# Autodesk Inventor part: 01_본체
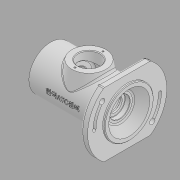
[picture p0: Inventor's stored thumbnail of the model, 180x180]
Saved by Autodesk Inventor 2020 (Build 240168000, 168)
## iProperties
Created: 2022-05
Part Number: 01_본체
Material: 일반
Document SubType Name: Modeling
Designer: User
Density: 1 g/cm^3
Appearance: 기본값
Author: User
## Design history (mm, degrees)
sketch "스케치1"
  geometry: L1 (0, 0)-(115, 0); L2 (0, 0)-(0, 32); L3 (0, 32)-(102, 32); L4 (102, 32)-(102, 58); L5 (102, 58)-(112, 58); L6 (112, 58)-(112, 36); L7 (112, 36)-(115, 36); L8 (115, 36)-(115, 0); L9 (0, 22.5)-(8, 22.5); L10 (8, 22.5)-(8, 24); L11 (8, 24)-(11, 24); L12 (11, 24)-(11, 22.5); L13 (11, 22.5)-(22, 22.5); L14 (22, 22.5)-(22, 17.5); L15 (22, 17.5)-(24.25, 17.5); L16 (24.25, 17.5)-(24.25, 18.5); L17 (24.25, 18.5)-(26, 18.5); L18 (26, 18.5)-(26, 17.5); L19 (26, 17.5)-(37, 17.5); L20 (37, 17.5)-(37, 27); L21 (37, 27)-(75, 27); L22 (75, 27)-(75, 17.5); L23 (75, 17.5)-(86, 17.5); L24 (86, 17.5)-(86, 15); L25 (86, 15)-(91, 15); L26 (91, 15)-(91, 11); L27 (91, 11)-(93.7, 11); L28 (93.7, 11)-(93.7, 15); L29 (101, 20)-(115, 30); L30 (100.3, 15)-(93.7, 15); L31 (101, 20)-(101, 15.404); L32 (101, 15.404)-(100.3, 15)
  constraints: 65 end point, 23 perpendicular, 8 point on line, 2 vertical, 1 horizontal, 1 parallel
  dimensions: "d0" = 115 distance of L1.start L1.end; "d1" = 102 distance of L2.end L3.end; "d2" = 3 distance of L6.end L7.end; "d3" = 72 diameter of L7 L1; "d4" = 64 diameter of L3 L1; "d5" = 116 diameter of L5 L1; "d6" = 14 distance from line of L8 L29.start; "d7" = 60 diameter of L29.end L1; "d8" = 40 diameter of L29.start L1; "d9" = 30 diameter of L30 L1; "d10" = 30 deg angle of L30 L32; "d11" = 0.7 horizontal distance of L30.start L31.end; "d12" = 7.3 distance between parallel lines of L28 L31; "d13" = 22 diameter of L27 L1; "d14" = 5 distance of L24.end L25.end; "d15" = 11 distance of L22.end L23.end; "d16" = 38 distance of L20.end L21.end; "d17" = 11 distance of L18.end L19.end; "d18" = 30 diameter of L25 L1; "d19" = 35 diameter of L23 L1; "d20" = 54 diameter of L21 L1; "d21" = 37 diameter of L17 L1; "d22" = 4 distance from line of L14.end L18; "d23" = 1.75 distance of L16.end L17.end; "d24" = 8 distance of L9.start L9.end; "d25" = 3 distance of L10.end L11.end; "d26" = 22 distance between parallel lines of L14 L2; "d27" = 45 diameter of L9 L1; "d28" = 48 diameter of L11 L1
revolve "회전1" sketch "스케치1" stored, may be unused: angle "d29" = 90 deg
sketch "스케치2"
  geometry: L1 (-33.985, 47)-(33.985, 47); L2 (-58, 0)-(58, 0); L3 (-33.985, -47)-(33.985, -47); A1 r 58 centre (0, 0) between (-33.985, 47) and (33.985, 47) reference; 2 further points
  constraints: 6 end point, 6 point on circle, 2 horizontal, 1 coincident, 1 midpoint, 1 parallel, 1 other
  dimensions: "d30" = 94 distance between parallel lines of L3 L1
extrude "돌출1" cut sketch "스케치2" extent not by distance; stored distance "d31" = 0; taper "d32" = 0 deg
sketch "스케치3"
  geometry: L1 (33.985, -47)-(-33.985, -47) reference; L2 (-33.985, 47)-(33.985, 47) reference; L3 (0, 0)-(48, 0); L4 (0, 0)-(36.77, 30.854); L5 (0, 0)-(-48, 0); L6 (0, 0)-(-36.77, -30.854); C1 r 36 at (0, 0) reference; A1 r 58 centre (0, 0) between (-33.985, 47) and (-33.985, -47) reference; A2 r 58 centre (0, 0) between (33.985, -47) and (33.985, 47) reference; A3 r 48 centre (0, 0) between (48, 0) and (36.77, 30.854); 2 further points
  constraints: 8 end point, 4 point on circle, 3 coincident, 2 horizontal, 1 centre point
  dimensions: "d33" = 48 radius of A3; "d34" = 40 deg angle of L3 L4; "d35" = 40 deg angle of L6 L5
hole "구멍1" sketch "스케치3" at (36.77, 30.854), (-36.77, -30.854) diameter "d36" = 8; stored, may be unused: countersink angle "d40" = 90 deg, drill point angle "d42" = 118 deg; dims "d37" = 12, "d38" = 4, "d39" = 2, "d41" = 8
sketch "스케치4"
  geometry: L1 (33.985, -47)-(-33.985, -47) reference; L2 (-33.985, 47)-(33.985, 47) reference; L3 (-48, 0)-(48, 0); C1 r 4 at (36.77, 30.854) reference; C2 r 4 at (-36.77, -30.854) reference; C3 r 36 at (0, 0) reference; A1 r 58 centre (0, 0) between (-33.985, 47) and (-33.985, -47) reference; A2 r 58 centre (0, 0) between (33.985, -47) and (33.985, 47) reference; A3 r 48 centre (0, 0) between (36.77, 30.854) and (-48, 0); A4 r 48 centre (0, 0) between (48, 0) and (36.77, 30.854); A5 r 52 centre (0, 0) between (52, 0) and (39.834, 33.425); A6 r 44 centre (0, 0) between (44, 0) and (33.706, 28.283); A7 r 4 centre (48, 0) between (44, 0) and (52, 0); A8 r 4 centre (36.77, 30.854) between (39.834, 33.425) and (33.706, 28.283); A9 r 48 centre (0, 0) between (-48, 0) and (-36.77, -30.854); A10 r 52 centre (0, 0) between (-52, 0) and (-39.834, -33.425); A11 r 44 centre (0, 0) between (-44, 0) and (-33.706, -28.283); A12 r 4 centre (-48, 0) between (-44, 0) and (-52, 0); A13 r 4 centre (-36.77, -30.854) between (-39.834, -33.425) and (-33.706, -28.283); 6 further points
  constraints: 23 point on circle, 11 centre point, 8 tangent, 4 coincident, 2 concentric, 2 end point, 1 horizontal, 1 midpoint
extrude "돌출2" cut sketch "스케치4" distance "d43" = 4.4; taper "d44" = 0 deg
sketch "스케치5"
  geometry: A1 r 4 centre (48, 0) between (44, 0) and (52, 0) reference; A2 r 52 centre (0, 0) between (52, 0) and (39.834, 33.425) reference; A3 r 4 centre (36.77, 30.854) between (33.706, 28.283) and (39.834, 33.425) reference; A4 r 44 centre (0, 0) between (44, 0) and (33.706, 28.283) reference; A5 r 4 centre (-48, 0) between (-44, 0) and (-52, 0) reference; A6 r 52 centre (0, 0) between (-52, 0) and (-39.834, -33.425) reference; A7 r 4 centre (-36.77, -30.854) between (-33.706, -28.283) and (-39.834, -33.425) reference; A8 r 44 centre (0, 0) between (-44, 0) and (-33.706, -28.283) reference; A9 r 50.25 centre (0, 0) between (50.25, 0) and (36.233, 34.818); A10 r 2.25 centre (48, 0) between (45.75, 0) and (50.25, 0); A11 r 45.75 centre (0, 0) between (45.75, 0) and (32.885, 31.806); A12 r 50.25 centre (0, 0) between (-50.25, 0) and (-40.58, -29.636); A13 r 2.25 centre (-48, 0) between (-45.75, 0) and (-50.25, 0); A14 r 45.75 centre (0, 0) between (-45.75, 0) and (-37.033, -26.862); 3 further points
  constraints: 16 point on circle, 6 centre point, 4 other
  dimensions: "d45" = 2.25 radius of A10; "d46" = 2.25 radius of A13
extrude "돌출3" cut sketch "스케치5" extent not by distance; stored distance "d47" = 0; taper "d48" = 0 deg
node "작업 평면1"
sketch "스케치6"
  geometry: C1 r 25 at (-56, 0); 1 further point
  constraints: 1 centre point, 1 horizontal alignment
  dimensions: "d50" = 25 radius of C1; "d51" = 56 distance of C1.centre point (0, 0)
extrude "돌출4" join sketch "스케치6" stored distance "d52" = 4.4; taper "d53" = 10 deg
sketch "스케치7"
  geometry: L1 (0, 0)-(0, 20.5); C1 r 25 at (0, 0) reference; 2 further points
  constraints: 2 end point, 1 coincident, 1 vertical
  dimensions: "d54" = 20.5 distance of L1.start L1.end
hole "구멍2" sketch "스케치7" at (0, 20.5) diameter "d55" = 2.62111; stored, may be unused: countersink angle "d59" = 90 deg, drill point angle "d61" = 118 deg; dims "d56" = 6, "d57" = 4, "d58" = 2, "d60" = 8
sketch "스케치8"
  geometry: C1 r 25 at (0, 0) reference; 2 further points
  constraints: 1 coincident
hole "구멍3" sketch "스케치8" at (0, 0) diameter "d65" = 32; stored, may be unused: countersink angle "d69" = 90 deg, drill point angle "d71" = 118 deg; dims "d66" = 6, "d67" = 4, "d68" = 2, "d70" = 8
fillet "모깎기1" dims "d72" = 0.5, "d73" = 0.6
fillet "모깎기2" dims "d74" = 3
chamfer "모따기1" distance "d75" = 1; stored, may be unused: second distance "d76" = 2, angle "d77" = 45 deg
fillet "모깎기3" dims "d78" = 3
node "작업 평면2"
sketch "스케치9"
  geometry: L1 (61, -46.4)-(61, 46.4) reference; 2 further points
  constraints: 1 horizontal alignment, 1 other
  dimensions: "d79" = 62 distance from line of point (-1, 0) L1
feature "엠보싱1" sketch "스케치9" dims "d0" = 115, "d1" = 102, "d2" = 3, "d3" = 72, "d4" = 64, "d5" = 116, "d6" = 14, "d7" = 60, "d8" = 40, "d9" = 30, "d10" = 30 deg, "d11" = 0.7, "d12" = 7.3, "d13" = 22, "d14" = 5, "d15" = 11, "d16" = 38, "d17" = 11, "d18" = 30, "d19" = 35, "d20" = 54, "d21" = 37, "d22" = 4, "d23" = 1.75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
feature "스레드1" dims "d82" = 8, "d83" = 0
node "솔리드1"
pattern_circular "원형 패턴1" dims angle "d63" = 360 deg
node "투영된 루프1"
node "투영된 루프2"
node "투영된 루프3"
node "투영된 루프4"
node "투영된 루프5"
feature "A9D066F2-1C7D-4E18-AEED-F7BC21143FA4" dims "d82" = 8, "d83" = 0
other parameters: "d49" = 38
